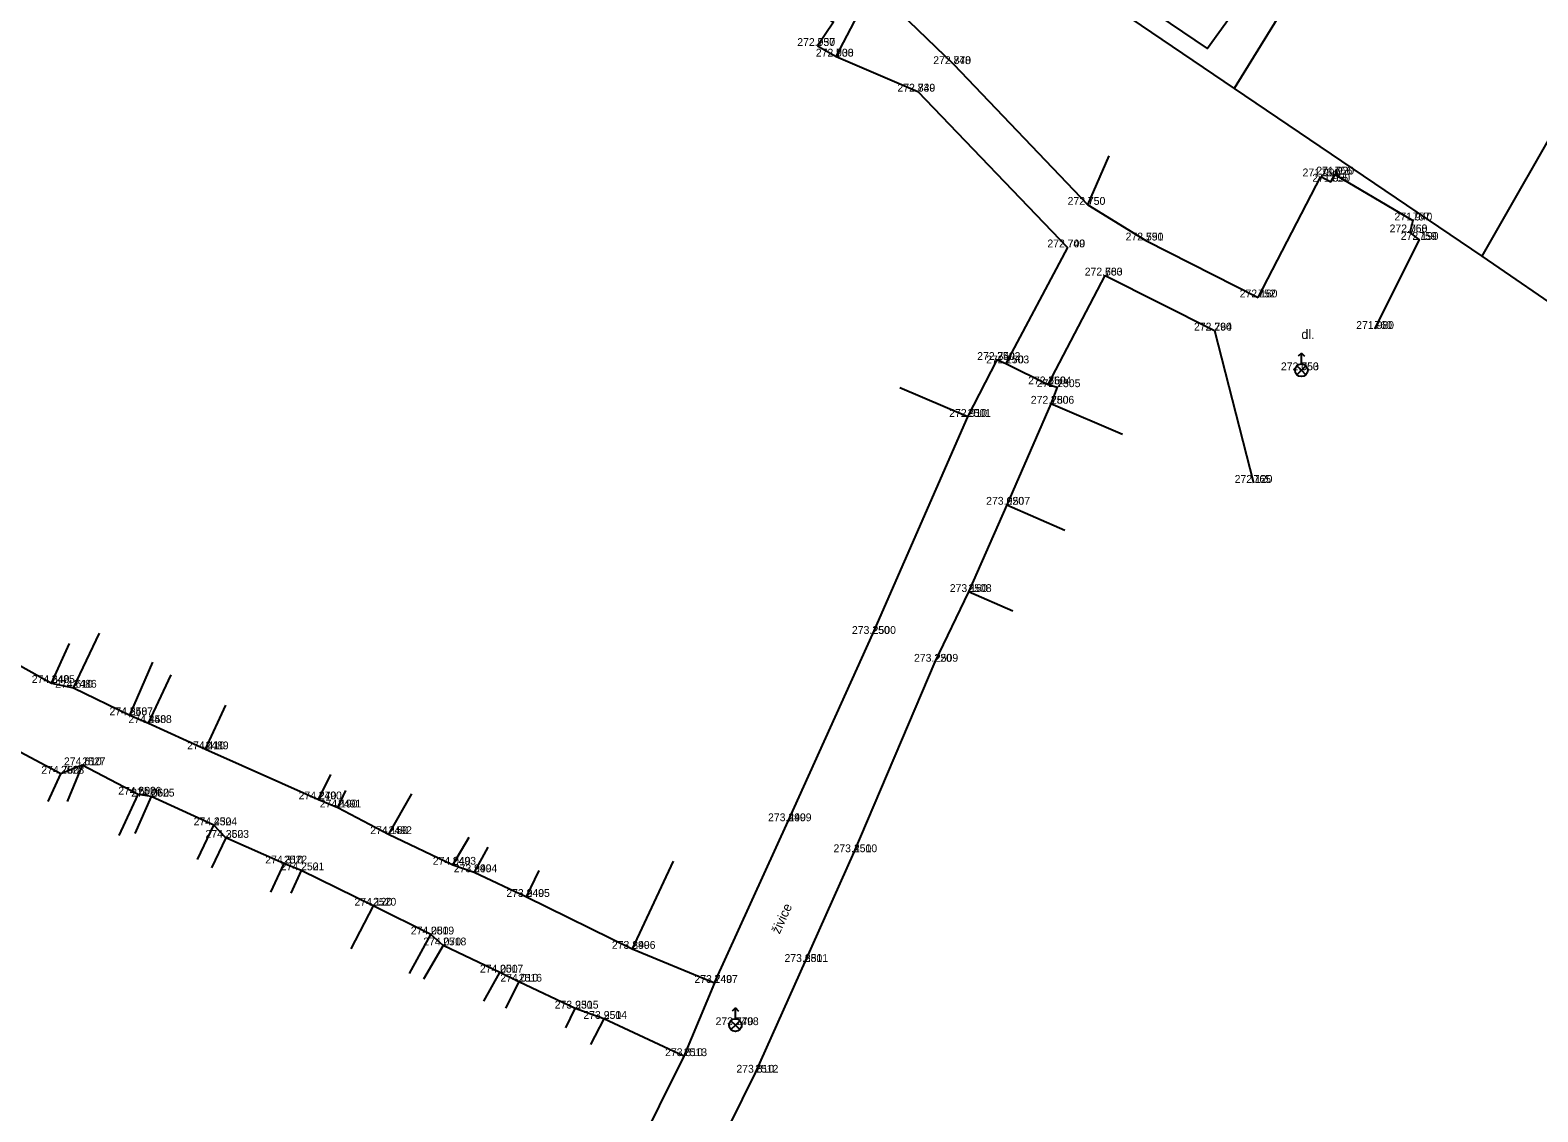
# Model space of a CAD drawing. Extents: x -776701 to -776081, y -974398 to -973771.
# Drawn here: x -776390.72 to -776342.51, y -974103.58 to -974068.99 of the extents above; entities that cross this region are included whole.
import ezdxf

# ---------------------------------------------------------------- set-up
doc = ezdxf.new("R2010")
doc.units = 0
for name, color, linetype in [('1 Body-bod', 7, 'Continuous'), ('10 Silnice-chodniky', 7, 'Continuous'), ('11 Rozhrani-nezpev zpev schody', 7, 'Continuous'), ('2 Body-cislo', 7, 'Continuous'), ('3 Body-vyska', 7, 'Continuous'), ('40 Popis-povrch', 7, 'Continuous'), ('58 Mobiliar', 7, 'Continuous'), ('7 Ploty', 7, 'Continuous'), ('8 Vstupy-pozemek', 7, 'Continuous'), ('Hranice parcel', 7, 'Continuous')]:
    doc.layers.add(name, color=color, linetype=linetype)

msp = doc.modelspace()

# ---------------------------------------------------------------- linework, layer by layer
at = {"layer": '1 Body-bod'}
for p, q in [((-776365.54, -974069.5), (-776365.54, -974069.5)), ((-776364.95, -974069.84), (-776364.95, -974069.84)), ((-776361.2, -974070.08), (-776361.2, -974070.08)), ((-776362.34, -974070.96), (-776362.34, -974070.96)), ((-776349.45, -974073.67), (-776349.45, -974073.67)), ((-776349.13, -974073.84), (-776349.13, -974073.84)), ((-776349, -974073.61), (-776349, -974073.61)), ((-776356.9, -974074.58), (-776356.9, -974074.58)), ((-776346.51, -974075.08), (-776346.51, -974075.08)), ((-776355.04, -974075.72), (-776355.04, -974075.72)), ((-776346.6, -974075.46), (-776346.6, -974075.46)), ((-776346.3, -974075.7), (-776346.3, -974075.7)), ((-776357.55, -974075.94), (-776357.55, -974075.94)), ((-776356.35, -974076.84), (-776356.35, -974076.84)), ((-776351.45, -974077.54), (-776351.45, -974077.54)), ((-776352.85, -974078.6), (-776352.85, -974078.6)), ((-776347.73, -974078.55), (-776347.73, -974078.55)), ((-776359.8, -974079.54), (-776359.8, -974079.54)), ((-776359.52, -974079.65), (-776359.52, -974079.65)), ((-776350.07, -974079.87), (-776350.07, -974079.87)), ((-776358.17, -974080.32), (-776358.17, -974080.32)), ((-776357.88, -974080.41), (-776357.88, -974080.41)), ((-776358.08, -974080.94), (-776358.08, -974080.94)), ((-776360.74, -974081.36), (-776360.74, -974081.36)), ((-776351.6, -974083.47), (-776351.6, -974083.47)), ((-776359.49, -974084.17), (-776359.49, -974084.17)), ((-776360.72, -974086.96), (-776360.72, -974086.96)), ((-776363.78, -974088.3), (-776363.78, -974088.3)), ((-776361.79, -974089.19), (-776361.79, -974089.19)), ((-776390.04, -974089.87), (-776390.04, -974089.87)), ((-776389.34, -974090.02), (-776389.34, -974090.02)), ((-776387.54, -974090.9), (-776387.54, -974090.9)), ((-776386.94, -974091.15), (-776386.94, -974091.15)), ((-776385.12, -974091.99), (-776385.12, -974091.99)), ((-776389.74, -974092.77), (-776389.74, -974092.77)), ((-776389.06, -974092.5), (-776389.06, -974092.5)), ((-776387.27, -974093.44), (-776387.27, -974093.44)), ((-776386.85, -974093.5), (-776386.85, -974093.5)), ((-776381.5, -974093.59), (-776381.5, -974093.59)), ((-776380.88, -974093.85), (-776380.88, -974093.85)), ((-776384.85, -974094.42), (-776384.85, -974094.42)), ((-776379.26, -974094.7), (-776379.26, -974094.7)), ((-776366.48, -974094.29), (-776366.48, -974094.29)), ((-776384.47, -974094.82), (-776384.47, -974094.82)), ((-776382.61, -974095.64), (-776382.61, -974095.64)), ((-776364.38, -974095.28), (-776364.38, -974095.28)), ((-776382.06, -974095.86), (-776382.06, -974095.86)), ((-776377.21, -974095.68), (-776377.21, -974095.68)), ((-776376.53, -974095.92), (-776376.53, -974095.92)), ((-776379.76, -974096.99), (-776379.76, -974096.99)), ((-776374.85, -974096.71), (-776374.85, -974096.71)), ((-776377.91, -974097.91), (-776377.91, -974097.91)), ((-776377.52, -974098.26), (-776377.52, -974098.26)), ((-776371.47, -974098.37), (-776371.47, -974098.37)), ((-776365.95, -974098.79), (-776365.95, -974098.79)), ((-776375.7, -974099.13), (-776375.7, -974099.13)), ((-776375.1, -974099.42), (-776375.1, -974099.42)), ((-776368.84, -974099.46), (-776368.84, -974099.46)), ((-776373.29, -974100.28), (-776373.29, -974100.28)), ((-776372.38, -974100.61), (-776372.38, -974100.61)), ((-776368.17, -974100.81), (-776368.17, -974100.81)), ((-776369.82, -974101.8), (-776369.82, -974101.8)), ((-776367.54, -974102.33), (-776367.54, -974102.33))]:
    msp.add_line(p, q, dxfattribs=at)
at = {"layer": '10 Silnice-chodniky'}
for points in [[(-776364.95, -974069.84), (-776363.78, -974067.59), (-776361.2, -974070.08), (-776356.9, -974074.58)], [(-776364.95, -974069.84), (-776362.34, -974070.96), (-776357.55, -974075.94), (-776359.52, -974079.65)], [(-776346.3, -974075.7), (-776347.73, -974078.55)], [(-776358.17, -974080.32), (-776356.35, -974076.84), (-776352.85, -974078.6), (-776351.6, -974083.47)], [(-776360.74, -974081.36), (-776359.8, -974079.54), (-776359.52, -974079.65), (-776358.17, -974080.32), (-776357.88, -974080.41), (-776358.08, -974080.94)], [(-776359.49, -974084.17), (-776360.72, -974086.96)], [(-776368.84, -974099.46), (-776369.82, -974101.8)]]:
    msp.add_lwpolyline(points, dxfattribs=at)
at = {"layer": '11 Rozhrani-nezpev zpev schody'}
for points in [[(-776365.54, -974069.5), (-776364.95, -974069.84)], [(-776390.04, -974089.87), (-776389.34, -974090.02)], [(-776387.54, -974090.9), (-776386.94, -974091.15)], [(-776385.12, -974091.99), (-776381.5, -974093.59)], [(-776389.06, -974092.5), (-776389.74, -974092.77)], [(-776386.85, -974093.5), (-776387.27, -974093.44)], [(-776380.88, -974093.85), (-776379.26, -974094.7)], [(-776384.47, -974094.82), (-776384.85, -974094.42)], [(-776379.76, -974096.99), (-776382.06, -974095.86)], [(-776377.21, -974095.68), (-776376.53, -974095.92)], [(-776374.85, -974096.71), (-776371.47, -974098.37)], [(-776377.52, -974098.26), (-776377.91, -974097.91)], [(-776375.1, -974099.42), (-776375.7, -974099.13)], [(-776372.38, -974100.61), (-776373.29, -974100.28)]]:
    msp.add_lwpolyline(points, dxfattribs=at)
at = {"layer": '58 Mobiliar'}
for p, q in [((-776350.07, -974079.87), (-776350.213, -974079.728)), ((-776350.07, -974079.32), (-776350.17, -974079.42)), ((-776350.07, -974079.669), (-776350.07, -974079.32)), ((-776350.07, -974079.32), (-776349.97, -974079.42)), ((-776350.07, -974079.87), (-776349.927, -974079.728)), ((-776350.07, -974079.87), (-776350.213, -974080.013)), ((-776350.07, -974079.87), (-776350.07, -974079.87)), ((-776350.07, -974079.87), (-776349.927, -974080.013)), ((-776368.17, -974100.26), (-776368.27, -974100.36)), ((-776368.17, -974100.608), (-776368.17, -974100.26)), ((-776368.17, -974100.26), (-776368.07, -974100.36)), ((-776368.17, -974100.81), (-776368.312, -974100.667)), ((-776368.17, -974100.81), (-776368.312, -974100.953)), ((-776368.17, -974100.81), (-776368.027, -974100.667)), ((-776368.17, -974100.81), (-776368.17, -974100.81)), ((-776368.17, -974100.81), (-776368.027, -974100.953))]:
    msp.add_line(p, q, dxfattribs=at)
for centre in [(-776350.07, -974079.87), (-776368.17, -974100.81)]:
    msp.add_circle(centre, 0.202, dxfattribs=at)
at = {"layer": '7 Ploty'}
for p, q in [((-776356.9, -974074.58), (-776356.218, -974073.018)), ((-776351.45, -974077.54), (-776349.45, -974073.67)), ((-776360.74, -974081.36), (-776362.911, -974080.435)), ((-776389.34, -974090.02), (-776388.511, -974088.277)), ((-776390.04, -974089.87), (-776389.462, -974088.605)), ((-776387.54, -974090.9), (-776386.797, -974089.208)), ((-776386.94, -974091.15), (-776386.217, -974089.614)), ((-776385.12, -974091.99), (-776384.462, -974090.574)), ((-776381.5, -974093.59), (-776381.11, -974092.794)), ((-776380.88, -974093.85), (-776380.626, -974093.304)), ((-776382.61, -974095.64), (-776383.041, -974096.56)), ((-776382.06, -974095.86), (-776382.392, -974096.587))]:
    msp.add_line(p, q, dxfattribs=at)
for points in [[(-776367.28, -974068.515), (-776366.71, -974067.63), (-776365.03, -974068.74), (-776365.54, -974069.5)], [(-776349.45, -974073.67), (-776349.13, -974073.84), (-776349, -974073.61)], [(-776356.9, -974074.58), (-776355.04, -974075.72)], [(-776346.51, -974075.08), (-776346.6, -974075.46), (-776346.3, -974075.7)], [(-776355.04, -974075.72), (-776351.45, -974077.54)], [(-776355.786, -974081.919), (-776358.08, -974080.94), (-776359.49, -974084.17), (-776357.638, -974084.984)], [(-776370.158, -974095.572), (-776371.47, -974098.37), (-776368.84, -974099.46), (-776366.48, -974094.29), (-776363.78, -974088.3), (-776360.74, -974081.36)], [(-776359.299, -974087.577), (-776360.72, -974086.96), (-776361.79, -974089.19), (-776364.38, -974095.28), (-776365.95, -974098.79), (-776367.54, -974102.33), (-776369.21, -974105.72), (-776371.71, -974110.25), (-776372.78, -974112.46), (-776374.65, -974116.01), (-776372.269, -974117.137)], [(-776391.87, -974088.86), (-776390.04, -974089.87)], [(-776389.34, -974090.02), (-776387.54, -974090.9)], [(-776386.94, -974091.15), (-776385.12, -974091.99)], [(-776390.153, -974093.654), (-776389.74, -974092.77), (-776391.52, -974091.83), (-776391.964, -974092.805)], [(-776387.878, -974094.745), (-776387.27, -974093.44), (-776389.06, -974092.5), (-776389.541, -974093.664)], [(-776385.369, -974095.516), (-776384.85, -974094.42), (-776386.85, -974093.5), (-776387.372, -974094.683)], [(-776381.5, -974093.59), (-776380.88, -974093.85)], [(-776378.528, -974093.414), (-776379.26, -974094.7), (-776377.21, -974095.68), (-776376.687, -974094.801)], [(-776382.06, -974095.86), (-776382.61, -974095.64), (-776384.47, -974094.82), (-776384.925, -974095.782)], [(-776376.084, -974095.121), (-776376.53, -974095.92), (-776374.85, -974096.71), (-776374.451, -974095.866)], [(-776378.59, -974099.159), (-776377.91, -974097.91), (-776379.76, -974096.99), (-776380.466, -974098.373)], [(-776376.211, -974100.048), (-776375.7, -974099.13), (-776377.52, -974098.26), (-776378.141, -974099.335)], [(-776373.593, -974100.898), (-776373.29, -974100.28), (-776375.1, -974099.42), (-776375.528, -974100.266)], [(-776369.82, -974101.8), (-776372.38, -974100.61), (-776372.806, -974101.426)], [(-776369.82, -974101.8), (-776372.2, -974106.59), (-776374.45, -974111.11), (-776375.63, -974113.31), (-776376.61, -974115.01), (-776378.01, -974117.64), (-776380.42, -974122.32), (-776384.06, -974129.11), (-776385.75, -974132.33)]]:
    msp.add_lwpolyline(points, dxfattribs=at)
at = {"layer": '8 Vstupy-pozemek'}
msp.add_lwpolyline([(-776349, -974073.61), (-776346.51, -974075.08)], dxfattribs=at)
at = {"layer": 'Hranice parcel'}
for p, q in [((-776344.68, -974058.65), (-776352.22, -974070.86)), ((-776334.7, -974059.4), (-776344.3, -974076.22)), ((-776352.22, -974070.86), (-776344.3, -974076.22)), ((-776344.3, -974076.22), (-776331.9, -974084.75))]:
    msp.add_line(p, q, dxfattribs=at)
for points in [[(-776437.4, -973999.42), (-776442.93, -974009.42), (-776352.22, -974070.86)], [(-776352.49, -974062.15), (-776349.31, -974064.37), (-776353.07, -974069.58), (-776356.23, -974067.44)]]:
    msp.add_lwpolyline(points, dxfattribs=at)

# ---------------------------------------------------------------- texts
at = {"layer": '2 Body-cislo'}
for s, p in [('737', (-776365.54, -974069.5)), ('738', (-776364.95, -974069.84)), ('748', (-776361.2, -974070.08)), ('739', (-776362.34, -974070.96)), ('754', (-776349.45, -974073.67)), ('756', (-776349, -974073.61)), ('755', (-776349.13, -974073.84)), ('750', (-776356.9, -974074.58)), ('757', (-776346.51, -974075.08)), ('758', (-776346.6, -974075.46)), ('749', (-776357.55, -974075.94)), ('751', (-776355.04, -974075.72)), ('759', (-776346.3, -974075.7)), ('763', (-776356.35, -974076.84)), ('752', (-776351.45, -974077.54)), ('760', (-776347.73, -974078.55)), ('764', (-776352.85, -974078.6)), ('2502', (-776359.8, -974079.54)), ('2503', (-776359.52, -974079.65)), ('753', (-776350.07, -974079.87)), ('2504', (-776358.17, -974080.32)), ('2505', (-776357.88, -974080.41)), ('2506', (-776358.08, -974080.94)), ('2501', (-776360.74, -974081.36)), ('765', (-776351.6, -974083.47)), ('2507', (-776359.49, -974084.17)), ('2508', (-776360.72, -974086.96)), ('2500', (-776363.78, -974088.3)), ('2509', (-776361.79, -974089.19)), ('2485', (-776390.04, -974089.87)), ('2486', (-776389.34, -974090.02)), ('2487', (-776387.54, -974090.9)), ('2488', (-776386.94, -974091.15)), ('2489', (-776385.12, -974091.99)), ('2527', (-776389.06, -974092.5)), ('2528', (-776389.74, -974092.77)), ('2526', (-776387.27, -974093.44)), ('2525', (-776386.85, -974093.5)), ('2490', (-776381.5, -974093.59)), ('2491', (-776380.88, -974093.85)), ('2524', (-776384.85, -974094.42)), ('2499', (-776366.48, -974094.29)), ('2523', (-776384.47, -974094.82)), ('2492', (-776379.26, -974094.7)), ('2510', (-776364.38, -974095.28)), ('2522', (-776382.61, -974095.64)), ('2521', (-776382.06, -974095.86)), ('2493', (-776377.21, -974095.68)), ('2494', (-776376.53, -974095.92)), ('2495', (-776374.85, -974096.71)), ('2520', (-776379.76, -974096.99)), ('2519', (-776377.91, -974097.91)), ('2518', (-776377.52, -974098.26)), ('2496', (-776371.47, -974098.37)), ('2511', (-776365.95, -974098.79)), ('2517', (-776375.7, -974099.13)), ('2516', (-776375.1, -974099.42)), ('2497', (-776368.84, -974099.46)), ('2515', (-776373.29, -974100.28)), ('2514', (-776372.38, -974100.61)), ('2498', (-776368.17, -974100.81)), ('2513', (-776369.82, -974101.8)), ('2512', (-776367.54, -974102.33))]:
    msp.add_text(s, height=0.25, dxfattribs=at).set_placement(p)
at = {"layer": '3 Body-vyska'}
for s, p in [('272.950', (-776366.192, -974069.5)), ('272.900', (-776365.599, -974069.84)), ('272.870', (-776361.843, -974070.08)), ('272.840', (-776362.989, -974070.96)), ('271.990', (-776350.033, -974073.67)), ('271.920', (-776349.593, -974073.61)), ('271.950', (-776349.719, -974073.84)), ('272.750', (-776357.546, -974074.58)), ('271.940', (-776347.093, -974075.08)), ('272.060', (-776347.249, -974075.46)), ('272.700', (-776358.193, -974075.94)), ('272.590', (-776355.692, -974075.72)), ('272.190', (-776346.893, -974075.7)), ('272.680', (-776356.999, -974076.84)), ('272.160', (-776352.043, -974077.54)), ('271.980', (-776348.317, -974078.55)), ('272.290', (-776353.505, -974078.6)), ('272.740', (-776360.439, -974079.54)), ('272.770', (-776360.153, -974079.65)), ('272.050', (-776350.725, -974079.87)), ('272.760', (-776358.809, -974080.32)), ('272.730', (-776358.532, -974080.41)), ('272.780', (-776358.723, -974080.94)), ('272.910', (-776361.333, -974081.36)), ('272.120', (-776352.204, -974083.47)), ('273.020', (-776360.151, -974084.17)), ('273.160', (-776361.315, -974086.96)), ('273.250', (-776364.444, -974088.3)), ('273.220', (-776362.458, -974089.19)), ('274.640', (-776390.674, -974089.87)), ('274.610', (-776389.923, -974090.02)), ('274.550', (-776388.188, -974090.9)), ('274.450', (-776387.581, -974091.15)), ('274.410', (-776385.703, -974091.99)), ('274.610', (-776389.643, -974092.5)), ('274.760', (-776390.368, -974092.77)), ('274.600', (-776387.908, -974093.44)), ('274.560', (-776387.491, -974093.5)), ('274.270', (-776382.139, -974093.59)), ('274.190', (-776381.463, -974093.85)), ('274.430', (-776385.497, -974094.42)), ('273.490', (-776367.127, -974094.29)), ('274.360', (-776385.117, -974094.82)), ('274.150', (-776379.849, -974094.7)), ('273.450', (-776365.033, -974095.28)), ('274.310', (-776383.205, -974095.64)), ('274.250', (-776382.712, -974095.86)), ('274.040', (-776377.848, -974095.68)), ('273.990', (-776377.177, -974095.92)), ('273.940', (-776375.497, -974096.71)), ('274.120', (-776380.353, -974096.99)), ('274.080', (-776378.552, -974097.91)), ('274.070', (-776378.152, -974098.26)), ('273.890', (-776372.121, -974098.37)), ('273.680', (-776366.601, -974098.79)), ('274.000', (-776376.342, -974099.13)), ('274.010', (-776375.687, -974099.42)), ('273.740', (-776369.481, -974099.46)), ('273.930', (-776373.949, -974100.28)), ('273.950', (-776373.033, -974100.61)), ('273.770', (-776368.805, -974100.81)), ('273.810', (-776370.419, -974101.8)), ('273.810', (-776368.139, -974102.33))]:
    msp.add_text(s, height=0.25, dxfattribs=at).set_placement(p)
at = {"layer": '40 Popis-povrch'}
msp.add_text('dl.', height=0.3, dxfattribs=at).set_placement((-776350.07, -974078.87))
msp.add_text('živice', height=0.3, rotation=65.8126, dxfattribs=at).set_placement((-776366.758, -974097.918))

doc.saveas('drawing.dxf')
